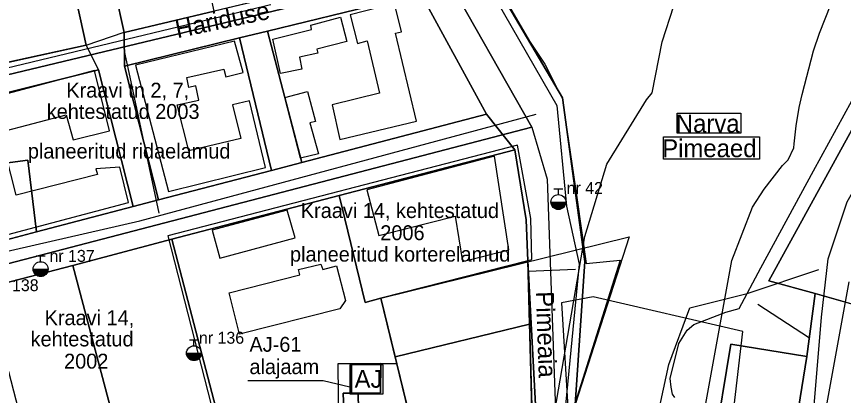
# Model space of a CAD drawing. Extents: x 728832 to 739469, y 6586263 to 6599699.
# Drawn here: x 738581.2 to 738858.8, y 6589955.2 to 6590082.3 of the extents above; entities that cross this region are included whole.
import ezdxf

# ---------------------------------------------------------------- set-up
doc = ezdxf.new("R2010")
doc.units = 0
for name, color, linetype in [('a_kalda_ekv', 7, 'Continuous'), ('a_kalda_piiranguv', 7, 'Continuous'), ('a_kalda_veekaitsev', 7, 'Continuous'), ('a_LK_III_kodukakk', 7, 'Continuous'), ('a_looduskaitse_voond', 7, 'Continuous'), ('a_piir', 7, 'Continuous'), ('dp_hoonestus', 7, 'Continuous'), ('PIIR', 7, 'Continuous'), ('plan_ala', 7, 'Continuous'), ('v_dp_kehtiv', 7, 'Continuous'), ('v_dp_kehtiv_tekst', 7, 'Continuous'), ('v_dp_kontaktvoond', 7, 'Continuous'), ('v_dp_krunt_objectID', 7, 'Continuous'), ('v_dp_kruntimise_tabel', 7, 'Continuous'), ('v_dp_tanav_tekst', 7, 'Continuous'), ('v_dp_transp_kergliiklejate_tanav', 7, 'Continuous'), ('v_olol_hüdrant', 7, 'Continuous'), ('v_olol_katastri_nimi', 7, 'Continuous'), ('v_olol_transp_jjt', 7, 'Continuous'), ('VKAEV', 7, 'Continuous')]:
    doc.layers.add(name, color=color, linetype=linetype)

# ---------------------------------------------------------------- blocks, each defined once
blk = doc.blocks.new('THYDRM_3')
at = {"layer": 'VKAEV'}
for p, q in [((-0.6, 1.8), (0.6, 1.8)), ((0, 1), (0, 1.8)), ((-1, 0), (1, 0))]:
    blk.add_line(p, q, dxfattribs=at)
blk.add_circle((0, 0), 1, dxfattribs=at)
for radius in [0.95, 0.9, 0.85, 0.8, 0.75, 0.7, 0.65, 0.6, 0.55, 0.5, 0.45, 0.4, 0.35, 0.3, 0.25, 0.2, 0.15, 0.1]:
    blk.add_arc((0, 0), radius, 180, 0, dxfattribs=at)

msp = doc.modelspace()

# ---------------------------------------------------------------- linework, layer by layer
at = {"layer": 'a_kalda_ekv'}
msp.add_lwpolyline([(738811.51, 6589946.37), (738821.34, 6590000.5), (738828.31, 6590018.34), (738832.18, 6590024.45), (738838.35, 6590032.31), (738840.22, 6590034.25), (738842.19, 6590038.3), (738842.25, 6590039.61), (738842.91, 6590045.71), (738843.96, 6590051.85), (738844.91, 6590056.22), (738848.79, 6590070.87), (738850.77, 6590076.81), (738854.63, 6590086.37)], dxfattribs=at)
at = {"layer": 'a_kalda_piiranguv'}
msp.add_lwpolyline([(738695.61, 6589728.48), (738706.15, 6589759.08), (738722.64, 6589798.76), (738722.69, 6589800.12), (738733.47, 6589829.62), (738734.51, 6589830.94), (738735.22, 6589840.26), (738737.86, 6589847.06), (738738.99, 6589862.11), (738741.2, 6589876.8), (738748.87, 6589910.57), (738751.45, 6589919.82), (738762.48, 6589953.16), (738771.98, 6590008.5), (738779.42, 6590032.77), (738792.73, 6590054.38), (738794.61, 6590056.71), (738798, 6590073.89), (738805.74, 6590098.09)], dxfattribs=at)
at = {"layer": 'a_kalda_veekaitsev'}
msp.add_lwpolyline([(738850.87, 6589939.22), (738860.7, 6589993.36)], dxfattribs=at)
at = {"layer": 'a_LK_III_kodukakk'}
msp.add_lwpolyline([(738774.8, 6589988.29), (738764.14, 6589986.28), (738769.19, 6589903.2), (738776.34, 6589779.97), (738793.46, 6589779), (738813.32, 6589799.46), (738821.04, 6589844.98), (738829.66, 6589892.22), (738832, 6589940.61), (738821.77, 6589948.75), (738824.98, 6589976.65)], close=True, dxfattribs=at)
at = {"layer": 'a_looduskaitse_voond'}
for points in [[(738742.33, 6590093.16), (738753.42, 6590074.13), (738758.55, 6590066.35), (738763.02, 6590057.58), (738764.34, 6590055.09), (738769.31, 6590021.66), (738772.45, 6589999.48), (738783.87, 6590000.64), (738768.64, 6589952.32)], [(738802.24, 6589954.47), (738801.41, 6589955.63), (738800.92, 6589957.94), (738800.59, 6589960.92), (738803.57, 6589972.67), (738806.38, 6589977.14), (738808.53, 6589978.96), (738819.29, 6589983.1), (738823.76, 6589984.42), (738831.04, 6589997.99), (738848.75, 6590030.6), (738861.66, 6590054.1)]]:
    msp.add_lwpolyline(points, dxfattribs=at)
for points in [[(738803.02, 6590049.9), (738824.39, 6590049.9), (738824.39, 6590043.2), (738803.02, 6590043.2)], [(738798.43, 6590041.97), (738830.63, 6590041.97), (738830.63, 6590034.44), (738798.43, 6590034.44)]]:
    msp.add_lwpolyline(points, close=True, dxfattribs=at)
at = {"layer": 'a_piir'}
for points in [[(738563.12, 6590074.99), (738565.47, 6590064.21), (738604.55, 6590072.77), (738589.58, 6590141.08), (738565.9, 6590135.88), (738567.17, 6590129.14), (738551.88, 6590126.25), (738561.89, 6590080.58), (738566.78, 6590081.55), (738567.97, 6590076.01)], [(738635.42, 6590138.88), (738606.8, 6590132.08), (738605.26, 6590131.72), (738617.33, 6590077.03), (738647.48, 6590084.18), (738643.18, 6590103.72), (738642.43, 6590107.1)], [(738714.48, 6590100.13), (738647.48, 6590084.18), (738617.33, 6590077.03), (738617.39, 6590065.7), (738656.06, 6590075.17), (738665.48, 6590077.48), (738716.96, 6590090.08)], [(738716.96, 6590090.08), (738665.48, 6590077.48), (738676.92, 6590033.37), (738738.99, 6590049.61)], [(738676.92, 6590033.37), (738665.48, 6590077.48), (738656.06, 6590075.17), (738666.76, 6590030.72)], [(738656.06, 6590075.17), (738617.39, 6590065.7), (738628.79, 6590020.79), (738666.76, 6590030.72)], [(738604.55, 6590072.77), (738565.47, 6590064.21), (738526.53, 6590055.67), (738527.2, 6590044.15), (738556.68, 6590051.52), (738608.66, 6590064.51)], [(738608.66, 6590064.51), (738556.68, 6590051.52), (738568.77, 6590005.09), (738570.92, 6590005.66), (738566.28, 6590031.73), (738585, 6590034.14), (738587.92, 6590010.1), (738620.33, 6590018.57)], [(738738.99, 6590049.61), (738676.92, 6590033.37), (738666.76, 6590030.72), (738628.79, 6590020.79), (738620.33, 6590018.57), (738587.92, 6590010.1), (738570.92, 6590005.66), (738568.77, 6590005.09), (738537.68, 6589996.96), (738518.66, 6589991.84), (738428.26, 6589970.5), (738386.7, 6589960.54), (738364.99, 6589956.62), (738367.22, 6589942.76), (738387.74, 6589947.59), (738436.23, 6589958.98), (738466.5, 6589966.08), (738515.12, 6589977.52), (738553.84, 6589986.61), (738571.13, 6589991.27), (738600.07, 6589998.83), (738633.27, 6590007.58), (738689.52, 6590022.24), (738748.53, 6590037.67)], [(738748.53, 6590037.67), (738689.52, 6590022.24), (738698.18, 6589986.41), (738703.51, 6589987.79), (738752.88, 6590000.39), (738752.27, 6590014.17)], [(738570.92, 6590005.66), (738587.92, 6590010.1), (738585, 6590034.14), (738566.28, 6590031.73)], [(738689.52, 6590022.24), (738633.27, 6590007.58), (738650.05, 6589943.32), (738691.26, 6589944.8), (738690.88, 6589955.96), (738693.65, 6589955.95), (738693.65, 6589965.82), (738703.46, 6589965.87), (738703.41, 6589956.03), (738695.91, 6589955.97), (738696.09, 6589944.86), (738713.89, 6589945.13), (738703.51, 6589987.79), (738698.18, 6589986.41)], [(738615.11, 6589942.17), (738650.05, 6589943.32), (738633.27, 6590007.58), (738600.07, 6589998.83)], [(738752.88, 6590000.39), (738703.51, 6589987.79), (738713.89, 6589945.13), (738714.33, 6589943.33), (738708.27, 6589918.18), (738755.04, 6589919)], [(738757.06, 6589920.61), (738752.88, 6590000.39), (738755.04, 6589919), (738757.14, 6589919.04)], [(738615.11, 6589942.17), (738600.07, 6589998.83), (738571.13, 6589991.27), (738581.73, 6589950.74), (738581.9, 6589941.15), (738610.26, 6589942.03)], [(738820.97, 6589972.38), (738815.28, 6589937.74), (738840.89, 6589933.53), (738846.51, 6589968.23)], [(738703.46, 6589965.87), (738693.65, 6589965.82), (738693.65, 6589955.95), (738695.91, 6589955.97), (738703.41, 6589956.03)], [(738696.09, 6589944.86), (738695.91, 6589955.97), (738693.65, 6589955.95), (738690.88, 6589955.96), (738691.26, 6589944.8)]]:
    msp.add_lwpolyline(points, close=True, dxfattribs=at)
for points in [[(738589.58, 6590141.08), (738604.55, 6590072.77), (738608.66, 6590064.51), (738620.33, 6590018.57), (738628.79, 6590020.79), (738617.39, 6590065.7), (738617.33, 6590077.03), (738605.26, 6590131.72)], [(738742.13, 6590093.07), (738764.49, 6590055.06), (738772.03, 6590000.09), (738768.72, 6589952.16), (738772.93, 6589857.45), (738773.4, 6589837.7), (738774.3, 6589799.69), (738773.02, 6589782.57), (738770.95, 6589773.79), (738772.21, 6589772.82), (738789.1, 6589772.13), (738816.58, 6589801.47), (738818.65, 6589803.67), (738821.12, 6589845.16), (738826.29, 6589871.7), (738836.38, 6589907.12), (738840.89, 6589933.53), (738815.28, 6589937.74), (738820.97, 6589972.38), (738846.51, 6589968.23), (738849.37, 6589989.36), (738833.77, 6589993.69), (738901.84, 6590117.49)], [(738901.84, 6590117.49), (738833.77, 6589993.69), (738849.37, 6589989.36), (738846.51, 6589968.23), (738840.89, 6589933.53), (738836.38, 6589907.12), (738826.29, 6589871.7), (738821.12, 6589845.16), (738818.65, 6589803.67), (738832.86, 6589803.2), (738833.85, 6589807.67), (738833.36, 6589816.28), (738834.18, 6589833.66), (738836, 6589849.88), (738844.44, 6589888.11), (738851.89, 6589911.28), (738858.18, 6589923.69), (738860.66, 6589942.56)], [(738716.96, 6590090.08), (738738.99, 6590049.61), (738748.53, 6590037.67), (738752.27, 6590014.17), (738752.88, 6590000.39), (738757.06, 6589920.61), (738757.14, 6589919.04), (738760.94, 6589844.8), (738761.22, 6589839.49), (738773.4, 6589837.7), (738772.93, 6589857.45), (738768.72, 6589952.16), (738772.03, 6590000.09), (738764.49, 6590055.06), (738742.13, 6590093.07)]]:
    msp.add_lwpolyline(points, dxfattribs=at)
at = {"layer": 'dp_hoonestus'}
msp.add_lwpolyline([(738703.51, 6589987.79), (738708.29, 6589968.15), (738753.45, 6589979.08), (738752.88, 6590000.39), (738703.51, 6589987.79)], close=True, dxfattribs=at)
at = {"layer": 'PIIR'}
for points in [[(738708.09, 6590086.74), (738693.18, 6590082.96), (738695.63, 6590073.33), (738698.86, 6590074.15), (738702.99, 6590056.62), (738687.18, 6590052.74), (738689.75, 6590041.1), (738715.46, 6590047.27), (738708.43, 6590076.77), (738710.46, 6590077.18)], [(738689.97, 6590082.11), (738692.09, 6590073.99), (738681.99, 6590071.38), (738682.3, 6590070.08), (738676.18, 6590068.71), (738676.97, 6590064.74), (738669.78, 6590063.23), (738667.23, 6590074.76), (738680.18, 6590078.02), (738680.02, 6590079.5)], [(738650.81, 6590064.66), (738651.43, 6590062.14), (738657.25, 6590063.54), (738654.35, 6590074.13), (738621.12, 6590066.07), (738632.21, 6590023.6), (738664.79, 6590031.64), (738659.35, 6590054.05), (738653.72, 6590052.69), (738656.48, 6590041.47), (738638.98, 6590037.32), (738635.07, 6590052.75), (738642.42, 6590054.33), (738641.4, 6590059.07), (738639.01, 6590058.56), (738638.32, 6590061.86)], [(738597.83, 6590049.37), (738600.22, 6590041), (738612.42, 6590044.02), (738607.38, 6590064.19), (738561.06, 6590051.98), (738572.63, 6590007.75), (738618.8, 6590019.95), (738615.86, 6590031.83), (738607.81, 6590031.2), (738608.38, 6590029.32), (738581.07, 6590022.4), (738575.62, 6590043.53)], [(738671.25, 6590055.22), (738678.86, 6590057.15), (738681.56, 6590047.15), (738679.65, 6590046.72), (738682.54, 6590036.32), (738676.54, 6590034.85)], [(738698.75, 6590024.15), (738702.76, 6590008.81), (738728.48, 6590015.3), (738730.89, 6590000.14), (738746.47, 6590004), (738741.6, 6590035.49)], [(738646.82, 6590010.71), (738649.42, 6590001.3), (738674.69, 6590008.06), (738672.06, 6590017.39)], [(738688.57, 6589998.7), (738691.6, 6589987.02), (738689.73, 6589984.26), (738656.04, 6589975.73), (738652.53, 6589989.58), (738676.24, 6589995.62), (738675.79, 6589997.4), (738683.36, 6589999.22), (738683.98, 6589997.48)]]:
    msp.add_lwpolyline(points, close=True, dxfattribs=at)
at = {"layer": 'plan_ala'}
msp.add_lwpolyline([(738773.4, 6589837.7), (738586.3, 6589865.2), (738586.3, 6589865.2), (738583.11, 6589865.67), (738577.13, 6589865.85), (738565.7, 6589866.14), (738565.45, 6589885.77), (738564.49, 6589941.05), (738581.9, 6589941.15), (738615.11, 6589942.17), (738650.05, 6589943.32), (738691.27, 6589944.8), (738696.09, 6589944.85), (738713.89, 6589945.13), (738703.51, 6589987.79), (738786.92, 6590008.4), (738768.72, 6589952.16)], close=True, dxfattribs=at)
at = {"layer": 'v_dp_kehtiv'}
for points in [[(738834.26, 6590139.1), (738901.84, 6590117.49), (738833.77, 6589993.69), (738849.37, 6589989.36), (738911.94, 6589971.59), (738937.72, 6590021.18), (738984.2, 6590114.69), (738993.34, 6590247.02), (738942.21, 6590350.94), (738908.53, 6590414.77), (738868.42, 6590397.1), (738843.38, 6590385.47), (738811.42, 6590370.68), (738843.25, 6590304.19), (738861.55, 6590265.91), (738881.66, 6590187.51), (738849.36, 6590185.31)], [(738833.77, 6589993.69), (738901.84, 6590117.49), (738834.26, 6590139.1), (738849.36, 6590185.31), (738881.66, 6590187.51), (738861.55, 6590265.91), (738843.25, 6590304.19), (738811.42, 6590370.68), (738868.42, 6590397.1), (738908.53, 6590414.77), (738942.21, 6590350.94), (738993.34, 6590247.02), (738984.2, 6590114.69), (738937.72, 6590021.18), (738911.94, 6589971.59), (738869.57, 6589983.62), (738849.37, 6589989.36)], [(738518.28, 6590048.41), (738724.34, 6590097.89), (738754.16, 6590045.25), (738560.05, 6589994.65), (738532.9, 6589987.47)], [(738518.28, 6590048.41), (738532.9, 6589987.47), (738560.05, 6589994.65), (738754.16, 6590045.25), (738724.34, 6590097.89)], [(738572.16, 6589949.69), (738560.05, 6589994.65), (738754.16, 6590045.25), (738754.16, 6590045.25), (738759.38, 6590027.73), (738763.29, 6589919.13), (738757.14, 6589919.04), (738708.27, 6589918.18), (738712.82, 6589937.07), (738573.1, 6589934.21)], [(738560.05, 6589994.65), (738754.16, 6590045.25), (738754.16, 6590045.25), (738759.38, 6590027.73), (738763.29, 6589919.13), (738757.14, 6589919.04), (738708.27, 6589918.18), (738712.82, 6589937.07), (738573.1, 6589934.21), (738572.16, 6589949.69)], [(738689.18, 6589965.94), (738689.18, 6589965.94), (738708.83, 6589965.94), (738703.51, 6589987.79), (738753.01, 6590000.42), (738754.21, 6590000.8), (738753.82, 6590014.6), (738749.4, 6590039.21), (738749.4, 6590039.21), (738631.94, 6590008.72), (738631.94, 6590008.72), (738648.75, 6589943.28), (738648.75, 6589943.28), (738648.75, 6589943.28), (738689.41, 6589944.25), (738689.41, 6589944.25)], [(738689.18, 6589965.94), (738689.18, 6589965.94), (738708.83, 6589965.94), (738703.51, 6589987.79), (738753.01, 6590000.42), (738754.21, 6590000.8), (738753.82, 6590014.6), (738749.4, 6590039.21), (738749.4, 6590039.21), (738631.94, 6590008.72), (738631.94, 6590008.72), (738648.75, 6589943.28), (738648.75, 6589943.28), (738648.75, 6589943.28), (738689.41, 6589944.25), (738689.41, 6589944.25)]]:
    msp.add_lwpolyline(points, close=True, dxfattribs=at)
at = {"layer": 'v_dp_kontaktvoond'}
msp.add_lwpolyline([(738514.55, 6590110.32), (738526.53, 6590055.67), (738604.55, 6590072.77), (738617.36, 6590077.07), (738714.48, 6590100.13)], dxfattribs=at)
at = {"layer": 'v_dp_kruntimise_tabel'}
msp.add_lwpolyline([(738693.03, 6589955.68), (738704.26, 6589955.68), (738704.26, 6589965.42), (738693.03, 6589965.42)], close=True, dxfattribs=at)
msp.add_lwpolyline([(738693.03, 6589957.94), (738684.08, 6589960.04), (738658.83, 6589960.04)], dxfattribs=at)
at = {"layer": 'v_dp_transp_kergliiklejate_tanav'}
msp.add_line((738752.97, 6589996.94), (738768.85, 6589997.57), dxfattribs=at)
at = {"layer": 'v_olol_katastri_nimi'}
for points in [[(738703.51, 6589987.79), (738713.21, 6589947.93), (738754.32, 6589946.29), (738752.88, 6590000.39)], [(738708.29, 6589968.15), (738703.51, 6589987.79), (738752.88, 6590000.39), (738753.45, 6589979.08)], [(738753.45, 6589979.08), (738754.32, 6589946.29), (738713.21, 6589947.93), (738708.29, 6589968.15)]]:
    msp.add_lwpolyline(points, close=True, dxfattribs=at)
at = {"layer": 'v_olol_transp_jjt'}
for p, q in [((738520.62, 6590051.41), (738728.63, 6590101.35)), ((738830.05, 6589985.79), (738847.37, 6589974.56))]:
    msp.add_line(p, q, dxfattribs=at)
for points in [[(738701.22, 6589304.96), (738722.43, 6589361.21), (738744.16, 6589429.66), (738746.01, 6589438.06), (738752.32, 6589484.93), (738757.68, 6589561.53), (738761.22, 6589598.39), (738763.23, 6589614.26), (738774.35, 6589665.72), (738786.24, 6589707.98), (738799.01, 6589743.38), (738822.48, 6589793.3), (738827.95, 6589808.63), (738827.95, 6589817.5), (738830.43, 6589848.34), (738832.8, 6589864.39), (738836.51, 6589886.76), (738847.81, 6589938.4), (738851.48, 6589981.51), (738853.67, 6590001.03), (738860.07, 6590020.16), (738885.77, 6590065.05), (738912.97, 6590120.99)], [(738739.83, 6590092.1), (738762.58, 6590052.49), (738765.8, 6590018.73), (738770.03, 6589999.23), (738765.16, 6589948.51), (738770.96, 6589801.22), (738770.96, 6589784.65), (738744.05, 6589687.94), (738732.19, 6589650.65), (738704.24, 6589618.95), (738677.81, 6589602.35), (738554.06, 6589547.05), (738495.74, 6589520.07)], [(738617.36, 6590070.72), (738618.88, 6590063.6), (738628.97, 6590016.41)], [(738555.43, 6589993.43), (738568.32, 6590001.39), (738622.57, 6590013.76), (738755.67, 6590049.57)], [(738776.52, 6589852.7), (738782.59, 6589864.56), (738782.59, 6589892.11), (738789.97, 6589918.46), (738800.13, 6589965.6), (738807.22, 6589984.64), (738826.43, 6589989.41), (738850.55, 6589997.43)]]:
    msp.add_lwpolyline(points, dxfattribs=at)

# ---------------------------------------------------------------- block references
at = {"layer": 'v_olol_hüdrant', "xscale": 2.5, "yscale": 2.5}
for p in [(738763.11, 6590020.08), (738589.25, 6589997.57), (738640.74, 6589969.36)]:
    msp.add_blockref('THYDRM_3', p, dxfattribs=at)

# ---------------------------------------------------------------- texts
at = {"layer": 'a_looduskaitse_voond'}
for s, p in [('Narva ', (738802.54, 6590043.46)), ('Pimeaed', (738797.96, 6590035.14))]:
    msp.add_text(s, height=6, dxfattribs=at).set_placement(p)
at = {"layer": 'v_dp_kehtiv_tekst'}
for s, p in [('Kraavi tn 2, 7,', (738597.88, 6590055.13)), ('kehtestatud 2003', (738591.31, 6590047.99)), ('planeeritud ridaelamud', (738584.96, 6590034.7)), ('Kraavi 14, kehtestatud  ', (738676.62, 6590014.73)), ('2006', (738703.3, 6590007.29)), ('planeeritud korterelamud', (738672.99, 6590000.1)), ('Kraavi 14,', (738590.59, 6589978.77)), ('kehtestatud ', (738585.9, 6589971.64)), ('2002', (738597.13, 6589964.19))]:
    msp.add_text(s, height=5, dxfattribs=at).set_placement(p)
at = {"layer": 'v_dp_krunt_objectID'}
for s, p in [('Narva ', (738802.54, 6590043.46)), ('Pimeaed', (738797.96, 6590035.14))]:
    msp.add_text(s, height=6, dxfattribs=at).set_placement(p)
at = {"layer": 'v_dp_kruntimise_tabel'}
for s, height, p in [('AJ-61', 5, (738659.37, 6589969.84)), ('alajaam', 5, (738659.37, 6589962.34)), ('AJ', 6, (738694.67, 6589957.76))]:
    msp.add_text(s, height=height, dxfattribs=at).set_placement(p)
at = {"layer": 'v_dp_tanav_tekst'}
for s, rotation, p in [('Hariduse', 11.8402, (738635.17, 6590075.05)), ('Pimeaia', 271.9233, (738755.54, 6589990.04))]:
    msp.add_text(s, height=6, rotation=rotation, dxfattribs=at).set_placement(p)
at = {"layer": 'v_olol_hüdrant'}
for s, p in [('nr 42', (738765.86, 6590022.8)), ('nr 137', (738592.23, 6590000.02)), ('nr 138', (738573.41, 6589990.18)), ('nr 136', (738642.42, 6589972.54))]:
    msp.add_text(s, height=4, dxfattribs=at).set_placement(p)

doc.saveas('drawing.dxf')
